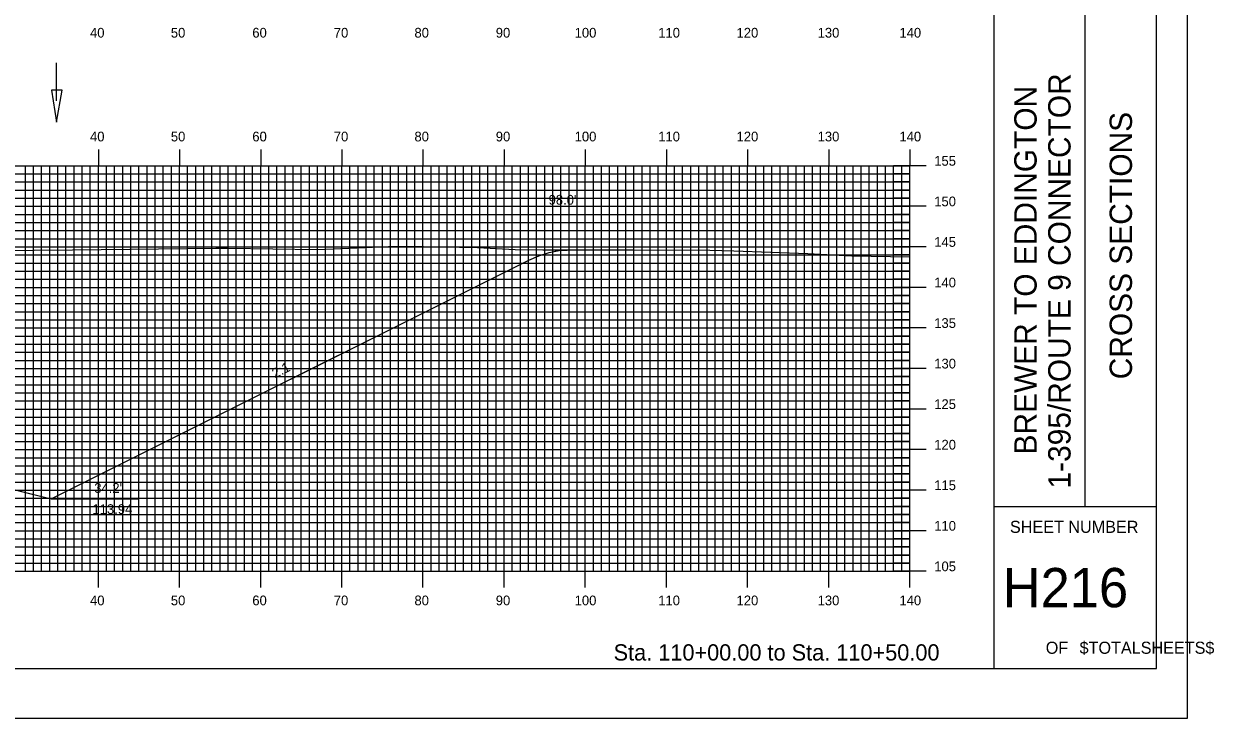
# Model space of a CAD drawing. Extents: x 1769268 to 1769611, y 442591 to 442811.
# Drawn here: x 1769464.3 to 1769611, y 442590.5 to 442676.2 of the extents above; entities that cross this region are included whole.
import ezdxf

# ---------------------------------------------------------------- set-up
doc = ezdxf.new("R2010")
doc.units = 0
for name, color, linetype in [('ANNOTATION', 7, 'Continuous'), ('BORDER', 7, 'Continuous'), ('D_Drainage_Ditch_Line', 7, 'Continuous'), ('D_Roadway_Centerline', 7, 'Continuous'), ('D_Roadway_SlopeLines', 7, 'Continuous'), ('D_Text_Standard', 7, 'Continuous'), ('H_V ANNOTATION', 7, 'Continuous'), ('MAJOR', 7, 'Continuous'), ('MINOR', 7, 'Continuous'), ('PDRAIN', 7, 'Continuous'), ('PLOT BOUNDARY', 7, 'Continuous'), ('S_Roadway_Centerline', 7, 'Continuous')]:
    doc.layers.add(name, color=color, linetype=linetype)

msp = doc.modelspace()

# ---------------------------------------------------------------- linework, layer by layer
at = {"layer": 'BORDER'}
for p, q in [((1769583.9, 442596.67), (1769583.9, 442806.67)), ((1769595.08, 442616.67), (1769595.08, 442686.67)), ((1769583.9, 442616.67), (1769603.9, 442616.67))]:
    msp.add_line(p, q, dxfattribs=at)
msp.add_lwpolyline([(1769283.9, 442596.67), (1769603.9, 442596.67), (1769603.9, 442806.67), (1769283.9, 442806.67)], close=True, dxfattribs=at)
at = {"layer": 'D_Drainage_Ditch_Line'}
msp.add_line((1769468.36, 442666.66), (1769468.36, 442671.36), dxfattribs=at)
msp.add_lwpolyline([(1769469.02, 442667.97), (1769467.71, 442667.97), (1769468.36, 442664.03)], close=True, dxfattribs=at)
at = {"layer": 'D_Roadway_Centerline'}
msp.add_lwpolyline([(1769463.68, 442618.6), (1769467.68, 442617.6), (1769467.68, 442617.6), (1769479.85, 442623.69), (1769526.54, 442647.04), (1769527.79, 442647.58), (1769529.04, 442647.97), (1769529.8, 442648.12), (1769530.29, 442648.21), (1769531.27, 442648.27), (1769531.54, 442648.29)], dxfattribs=at)
at = {"layer": 'D_Roadway_SlopeLines'}
for points in [[(1769467.68, 442617.6), (1769526.54, 442647.04), (1769527.79, 442647.58), (1769529.04, 442647.97), (1769530.29, 442648.21), (1769531.54, 442648.29)], [(1769453.5, 442621.15), (1769467.68, 442617.6)]]:
    msp.add_lwpolyline(points, dxfattribs=at)
at = {"layer": 'MAJOR'}
for p, q in [((1769473.5, 442660.67), (1769473.5, 442658.67)), ((1769483.5, 442660.67), (1769483.5, 442658.67)), ((1769493.5, 442660.67), (1769493.5, 442658.67)), ((1769503.5, 442660.67), (1769503.5, 442658.67)), ((1769513.5, 442660.67), (1769513.5, 442658.67)), ((1769523.5, 442660.67), (1769523.5, 442658.67)), ((1769533.5, 442660.67), (1769533.5, 442658.67)), ((1769543.5, 442660.67), (1769543.5, 442658.67)), ((1769553.5, 442660.67), (1769553.5, 442658.67)), ((1769563.5, 442660.67), (1769563.5, 442658.67)), ((1769573.5, 442660.67), (1769573.5, 442658.67)), ((1769293.5, 442658.67), (1769573.5, 442658.67)), ((1769293.5, 442658.67), (1769573.5, 442658.67)), ((1769473.5, 442608.67), (1769473.5, 442658.67)), ((1769483.5, 442608.67), (1769483.5, 442658.67)), ((1769493.5, 442608.67), (1769493.5, 442658.67)), ((1769503.5, 442608.67), (1769503.5, 442658.67)), ((1769513.5, 442608.67), (1769513.5, 442658.67)), ((1769523.5, 442608.67), (1769523.5, 442658.67)), ((1769533.5, 442608.67), (1769533.5, 442658.67)), ((1769543.5, 442608.67), (1769543.5, 442658.67)), ((1769553.5, 442608.67), (1769553.5, 442658.67)), ((1769563.5, 442608.67), (1769563.5, 442658.67)), ((1769575.51, 442658.67), (1769571.5, 442658.67)), ((1769573.5, 442608.67), (1769573.5, 442658.67)), ((1769573.5, 442608.67), (1769573.5, 442658.67)), ((1769293.5, 442653.67), (1769573.5, 442653.67)), ((1769575.51, 442653.67), (1769571.5, 442653.67)), ((1769293.5, 442648.67), (1769573.5, 442648.67)), ((1769575.51, 442648.67), (1769571.5, 442648.67)), ((1769293.5, 442643.67), (1769573.5, 442643.67)), ((1769575.51, 442643.67), (1769571.5, 442643.67)), ((1769293.5, 442638.67), (1769573.5, 442638.67)), ((1769575.51, 442638.67), (1769571.5, 442638.67)), ((1769293.5, 442633.67), (1769573.5, 442633.67)), ((1769575.51, 442633.67), (1769571.5, 442633.67)), ((1769293.5, 442628.67), (1769573.5, 442628.67)), ((1769575.51, 442628.67), (1769571.5, 442628.67)), ((1769293.5, 442623.67), (1769573.5, 442623.67)), ((1769575.51, 442623.67), (1769571.5, 442623.67)), ((1769293.5, 442618.67), (1769573.5, 442618.67)), ((1769575.51, 442618.67), (1769571.5, 442618.67)), ((1769293.5, 442613.67), (1769573.5, 442613.67)), ((1769575.51, 442613.67), (1769571.5, 442613.67)), ((1769293.5, 442608.67), (1769573.5, 442608.67)), ((1769293.5, 442608.67), (1769573.5, 442608.67)), ((1769473.5, 442606.66), (1769473.5, 442608.67)), ((1769483.5, 442606.66), (1769483.5, 442608.67)), ((1769493.5, 442606.66), (1769493.5, 442608.67)), ((1769503.5, 442606.66), (1769503.5, 442608.67)), ((1769513.5, 442606.66), (1769513.5, 442608.67)), ((1769523.5, 442606.66), (1769523.5, 442608.67)), ((1769533.5, 442606.66), (1769533.5, 442608.67)), ((1769543.5, 442606.66), (1769543.5, 442608.67)), ((1769553.5, 442606.66), (1769553.5, 442608.67)), ((1769563.5, 442606.66), (1769563.5, 442608.67)), ((1769575.51, 442608.67), (1769571.5, 442608.67)), ((1769573.5, 442606.66), (1769573.5, 442608.67))]:
    msp.add_line(p, q, dxfattribs=at)
at = {"layer": 'MINOR'}
for p, q in [((1769464.5, 442608.67), (1769464.5, 442658.67)), ((1769465.5, 442608.67), (1769465.5, 442658.67)), ((1769466.5, 442608.67), (1769466.5, 442658.67)), ((1769467.5, 442608.67), (1769467.5, 442658.67)), ((1769468.5, 442608.67), (1769468.5, 442658.67)), ((1769469.5, 442608.67), (1769469.5, 442658.67)), ((1769470.5, 442608.67), (1769470.5, 442658.67)), ((1769471.5, 442608.67), (1769471.5, 442658.67)), ((1769472.5, 442608.67), (1769472.5, 442658.67)), ((1769474.5, 442608.67), (1769474.5, 442658.67)), ((1769475.5, 442608.67), (1769475.5, 442658.67)), ((1769476.5, 442608.67), (1769476.5, 442658.67)), ((1769477.5, 442608.67), (1769477.5, 442658.67)), ((1769478.5, 442608.67), (1769478.5, 442658.67)), ((1769479.5, 442608.67), (1769479.5, 442658.67)), ((1769480.5, 442608.67), (1769480.5, 442658.67)), ((1769481.5, 442608.67), (1769481.5, 442658.67)), ((1769482.5, 442608.67), (1769482.5, 442658.67)), ((1769484.5, 442608.67), (1769484.5, 442658.67)), ((1769485.5, 442608.67), (1769485.5, 442658.67)), ((1769486.5, 442608.67), (1769486.5, 442658.67)), ((1769487.5, 442608.67), (1769487.5, 442658.67)), ((1769488.5, 442608.67), (1769488.5, 442658.67)), ((1769489.5, 442608.67), (1769489.5, 442658.67)), ((1769490.5, 442608.67), (1769490.5, 442658.67)), ((1769491.5, 442608.67), (1769491.5, 442658.67)), ((1769492.5, 442608.67), (1769492.5, 442658.67)), ((1769494.5, 442608.67), (1769494.5, 442658.67)), ((1769495.5, 442608.67), (1769495.5, 442658.67)), ((1769496.5, 442608.67), (1769496.5, 442658.67)), ((1769497.5, 442608.67), (1769497.5, 442658.67)), ((1769498.5, 442608.67), (1769498.5, 442658.67)), ((1769499.5, 442608.67), (1769499.5, 442658.67)), ((1769500.5, 442608.67), (1769500.5, 442658.67)), ((1769501.5, 442608.67), (1769501.5, 442658.67)), ((1769502.5, 442608.67), (1769502.5, 442658.67)), ((1769504.5, 442608.67), (1769504.5, 442658.67)), ((1769505.5, 442608.67), (1769505.5, 442658.67)), ((1769506.5, 442608.67), (1769506.5, 442658.67)), ((1769507.5, 442608.67), (1769507.5, 442658.67)), ((1769508.5, 442608.67), (1769508.5, 442658.67)), ((1769509.5, 442608.67), (1769509.5, 442658.67)), ((1769510.5, 442608.67), (1769510.5, 442658.67)), ((1769511.5, 442608.67), (1769511.5, 442658.67)), ((1769512.5, 442608.67), (1769512.5, 442658.67)), ((1769514.5, 442608.67), (1769514.5, 442658.67)), ((1769515.5, 442608.67), (1769515.5, 442658.67)), ((1769516.5, 442608.67), (1769516.5, 442658.67)), ((1769517.5, 442608.67), (1769517.5, 442658.67)), ((1769518.5, 442608.67), (1769518.5, 442658.67)), ((1769519.5, 442608.67), (1769519.5, 442658.67)), ((1769520.5, 442608.67), (1769520.5, 442658.67)), ((1769521.5, 442608.67), (1769521.5, 442658.67)), ((1769522.5, 442608.67), (1769522.5, 442658.67)), ((1769524.5, 442608.67), (1769524.5, 442658.67)), ((1769525.5, 442608.67), (1769525.5, 442658.67)), ((1769526.5, 442608.67), (1769526.5, 442658.67)), ((1769527.5, 442608.67), (1769527.5, 442658.67)), ((1769528.5, 442608.67), (1769528.5, 442658.67)), ((1769529.5, 442608.67), (1769529.5, 442658.67)), ((1769530.5, 442608.67), (1769530.5, 442658.67)), ((1769531.5, 442608.67), (1769531.5, 442658.67)), ((1769532.5, 442608.67), (1769532.5, 442658.67)), ((1769534.5, 442608.67), (1769534.5, 442658.67)), ((1769535.5, 442608.67), (1769535.5, 442658.67)), ((1769536.5, 442608.67), (1769536.5, 442658.67)), ((1769537.5, 442608.67), (1769537.5, 442658.67)), ((1769538.5, 442608.67), (1769538.5, 442658.67)), ((1769539.5, 442608.67), (1769539.5, 442658.67)), ((1769540.5, 442608.67), (1769540.5, 442658.67)), ((1769541.5, 442608.67), (1769541.5, 442658.67)), ((1769542.5, 442608.67), (1769542.5, 442658.67)), ((1769544.5, 442608.67), (1769544.5, 442658.67)), ((1769545.5, 442608.67), (1769545.5, 442658.67)), ((1769546.5, 442608.67), (1769546.5, 442658.67)), ((1769547.5, 442608.67), (1769547.5, 442658.67)), ((1769548.5, 442608.67), (1769548.5, 442658.67)), ((1769549.5, 442608.67), (1769549.5, 442658.67)), ((1769550.5, 442608.67), (1769550.5, 442658.67)), ((1769551.5, 442608.67), (1769551.5, 442658.67)), ((1769552.5, 442608.67), (1769552.5, 442658.67)), ((1769554.5, 442608.67), (1769554.5, 442658.67)), ((1769555.5, 442608.67), (1769555.5, 442658.67)), ((1769556.5, 442608.67), (1769556.5, 442658.67)), ((1769557.5, 442608.67), (1769557.5, 442658.67)), ((1769558.5, 442608.67), (1769558.5, 442658.67)), ((1769559.5, 442608.67), (1769559.5, 442658.67)), ((1769560.5, 442608.67), (1769560.5, 442658.67)), ((1769561.5, 442608.67), (1769561.5, 442658.67)), ((1769562.5, 442608.67), (1769562.5, 442658.67)), ((1769564.5, 442608.67), (1769564.5, 442658.67)), ((1769565.5, 442608.67), (1769565.5, 442658.67)), ((1769566.5, 442608.67), (1769566.5, 442658.67)), ((1769567.5, 442608.67), (1769567.5, 442658.67)), ((1769568.5, 442608.67), (1769568.5, 442658.67)), ((1769569.5, 442608.67), (1769569.5, 442658.67)), ((1769570.5, 442608.67), (1769570.5, 442658.67)), ((1769571.5, 442608.67), (1769571.5, 442658.67)), ((1769572.5, 442608.67), (1769572.5, 442658.67)), ((1769293.5, 442657.67), (1769573.5, 442657.67)), ((1769573.5, 442657.67), (1769571.5, 442657.67)), ((1769293.5, 442656.67), (1769573.5, 442656.67)), ((1769293.5, 442655.67), (1769573.5, 442655.67)), ((1769573.5, 442656.67), (1769571.5, 442656.67)), ((1769573.5, 442655.67), (1769571.5, 442655.67)), ((1769293.5, 442654.67), (1769573.5, 442654.67)), ((1769573.5, 442654.67), (1769571.5, 442654.67)), ((1769293.5, 442652.67), (1769573.5, 442652.67)), ((1769573.5, 442652.67), (1769571.5, 442652.67)), ((1769293.5, 442651.67), (1769573.5, 442651.67)), ((1769573.5, 442651.67), (1769571.5, 442651.67)), ((1769293.5, 442650.67), (1769573.5, 442650.67)), ((1769293.5, 442649.67), (1769573.5, 442649.67)), ((1769573.5, 442650.67), (1769571.5, 442650.67)), ((1769573.5, 442649.67), (1769571.5, 442649.67)), ((1769293.5, 442647.67), (1769573.5, 442647.67)), ((1769293.5, 442646.67), (1769573.5, 442646.67)), ((1769573.5, 442647.67), (1769571.5, 442647.67)), ((1769573.5, 442646.67), (1769571.5, 442646.67)), ((1769293.5, 442645.67), (1769573.5, 442645.67)), ((1769573.5, 442645.67), (1769571.5, 442645.67)), ((1769293.5, 442644.67), (1769573.5, 442644.67)), ((1769573.5, 442644.67), (1769571.5, 442644.67)), ((1769293.5, 442642.67), (1769573.5, 442642.67)), ((1769573.5, 442642.67), (1769571.5, 442642.67)), ((1769293.5, 442641.67), (1769573.5, 442641.67)), ((1769293.5, 442640.67), (1769573.5, 442640.67)), ((1769573.5, 442641.67), (1769571.5, 442641.67)), ((1769573.5, 442640.67), (1769571.5, 442640.67)), ((1769293.5, 442639.67), (1769573.5, 442639.67)), ((1769573.5, 442639.67), (1769571.5, 442639.67)), ((1769293.5, 442637.67), (1769573.5, 442637.67)), ((1769573.5, 442637.67), (1769571.5, 442637.67)), ((1769293.5, 442636.67), (1769573.5, 442636.67)), ((1769573.5, 442636.67), (1769571.5, 442636.67)), ((1769293.5, 442635.67), (1769573.5, 442635.67)), ((1769573.5, 442635.67), (1769571.5, 442635.67)), ((1769293.5, 442634.67), (1769573.5, 442634.67)), ((1769573.5, 442634.67), (1769571.5, 442634.67)), ((1769293.5, 442632.67), (1769573.5, 442632.67)), ((1769573.5, 442632.67), (1769571.5, 442632.67)), ((1769293.5, 442631.67), (1769573.5, 442631.67)), ((1769293.5, 442630.67), (1769573.5, 442630.67)), ((1769573.5, 442631.67), (1769571.5, 442631.67)), ((1769573.5, 442630.67), (1769571.5, 442630.67)), ((1769293.5, 442629.67), (1769573.5, 442629.67)), ((1769573.5, 442629.67), (1769571.5, 442629.67)), ((1769293.5, 442627.67), (1769573.5, 442627.67)), ((1769573.5, 442627.67), (1769571.5, 442627.67)), ((1769293.5, 442626.67), (1769573.5, 442626.67)), ((1769573.5, 442626.67), (1769571.5, 442626.67)), ((1769293.5, 442625.67), (1769573.5, 442625.67)), ((1769293.5, 442624.67), (1769573.5, 442624.67)), ((1769573.5, 442625.67), (1769571.5, 442625.67)), ((1769573.5, 442624.67), (1769571.5, 442624.67)), ((1769293.5, 442622.67), (1769573.5, 442622.67)), ((1769293.5, 442621.67), (1769573.5, 442621.67)), ((1769573.5, 442622.67), (1769571.5, 442622.67)), ((1769573.5, 442621.67), (1769571.5, 442621.67)), ((1769293.5, 442620.67), (1769573.5, 442620.67)), ((1769573.5, 442620.67), (1769571.5, 442620.67)), ((1769293.5, 442619.67), (1769573.5, 442619.67)), ((1769573.5, 442619.67), (1769571.5, 442619.67)), ((1769293.5, 442617.67), (1769573.5, 442617.67)), ((1769573.5, 442617.67), (1769571.5, 442617.67)), ((1769293.5, 442616.67), (1769573.5, 442616.67)), ((1769293.5, 442615.67), (1769573.5, 442615.67)), ((1769573.5, 442616.67), (1769571.5, 442616.67)), ((1769573.5, 442615.67), (1769571.5, 442615.67)), ((1769293.5, 442614.67), (1769573.5, 442614.67)), ((1769573.5, 442614.67), (1769571.5, 442614.67)), ((1769293.5, 442612.67), (1769573.5, 442612.67)), ((1769293.5, 442611.67), (1769573.5, 442611.67)), ((1769573.5, 442612.67), (1769571.5, 442612.67)), ((1769573.5, 442611.67), (1769571.5, 442611.67)), ((1769293.5, 442610.67), (1769573.5, 442610.67)), ((1769573.5, 442610.67), (1769571.5, 442610.67)), ((1769293.5, 442609.67), (1769573.5, 442609.67)), ((1769573.5, 442609.67), (1769571.5, 442609.67))]:
    msp.add_line(p, q, dxfattribs=at)
at = {"layer": 'PDRAIN'}
msp.add_line((1769467.68, 442617.6), (1769478.45, 442617.6), dxfattribs=at)
at = {"layer": 'PLOT BOUNDARY'}
msp.add_lwpolyline([(1769267.72, 442590.55), (1769607.72, 442590.55), (1769607.72, 442810.55), (1769267.72, 442810.55)], close=True, dxfattribs=at)
at = {"layer": 'S_Roadway_Centerline'}
msp.add_lwpolyline([(1769456.07, 442648.17), (1769470.31, 442648.28), (1769487.99, 442648.52), (1769489.53, 442648.51), (1769500.48, 442648.33), (1769509.26, 442648.72), (1769513.56, 442648.72), (1769520.23, 442648.58), (1769524.87, 442648.36), (1769528.27, 442648.29), (1769539.51, 442648.29), (1769548.86, 442648.24), (1769551.8, 442648.17), (1769560.91, 442647.84), (1769566.35, 442647.55), (1769573.5, 442647.44)], dxfattribs=at)

# ---------------------------------------------------------------- texts
at = {"layer": 'ANNOTATION'}
msp.add_text('2:1', height=1.2, rotation=26.5652, dxfattribs=at).set_placement((1769495.26, 442632.43))
for s, p in [("34.2'", (1769472.99, 442618.33)), ('113.94', (1769472.77, 442615.73))]:
    msp.add_text(s, height=1.2, dxfattribs=at).set_placement(p)
at = {"layer": 'BORDER'}
for s, p in [('1-395/ROUTE 9 CONNECTOR', (1769593.3, 442618.87)), ('BREWER TO EDDINGTON', (1769589.12, 442623.07)), ('CROSS SECTIONS', (1769600.87, 442632.34))]:
    msp.add_text(s, height=2.7557, rotation=90, dxfattribs=at).set_placement(p)
for s, height, p in [('SHEET NUMBER', 1.4905, (1769585.83, 442613.4)), ('H216', 4.839, (1769584.93, 442604.23)), ('OF', 1.491, (1769590.24, 442598.49)), ('$TOTALSHEETS$', 1.4905, (1769594.41, 442598.49))]:
    msp.add_text(s, height=height, dxfattribs=at).set_placement(p)
at = {"layer": 'D_Text_Standard'}
msp.add_text("98.0'", height=1.2, dxfattribs=at).set_placement((1769528.98, 442653.87))
at = {"layer": 'H_V ANNOTATION'}
for s, height, p in [('40', 1.2, (1769472.47, 442674.47)), ('50', 1.2, (1769482.43, 442674.47)), ('60', 1.2, (1769492.47, 442674.47)), ('70', 1.2, (1769502.51, 442674.47)), ('80', 1.2, (1769512.45, 442674.47)), ('90', 1.2, (1769522.47, 442674.47)), ('100', 1.2, (1769532.19, 442674.47)), ('110', 1.2, (1769542.49, 442674.47)), ('120', 1.2, (1769552.14, 442674.47)), ('130', 1.2, (1769562.13, 442674.47)), ('140', 1.2, (1769572.21, 442674.47)), ('40', 1.2, (1769472.47, 442661.67)), ('50', 1.2, (1769482.43, 442661.67)), ('60', 1.2, (1769492.47, 442661.67)), ('70', 1.2, (1769502.51, 442661.67)), ('80', 1.2, (1769512.45, 442661.67)), ('90', 1.2, (1769522.47, 442661.67)), ('100', 1.2, (1769532.19, 442661.67)), ('110', 1.2, (1769542.49, 442661.67)), ('120', 1.2, (1769552.14, 442661.67)), ('130', 1.2, (1769562.13, 442661.67)), ('140', 1.2, (1769572.21, 442661.67)), ('155', 1.2, (1769576.5, 442658.67)), ('150', 1.2, (1769576.5, 442653.67)), ('145', 1.2, (1769576.5, 442648.67)), ('140', 1.2, (1769576.5, 442643.67)), ('135', 1.2, (1769576.5, 442638.67)), ('130', 1.2, (1769576.5, 442633.67)), ('125', 1.2, (1769576.5, 442628.67)), ('120', 1.2, (1769576.5, 442623.67)), ('115', 1.2, (1769576.5, 442618.67)), ('110', 1.2, (1769576.5, 442613.67)), ('105', 1.2, (1769576.5, 442608.67)), ('40', 1.2, (1769472.47, 442604.47)), ('50', 1.2, (1769482.43, 442604.47)), ('60', 1.2, (1769492.47, 442604.47)), ('70', 1.2, (1769502.51, 442604.47)), ('80', 1.2, (1769512.45, 442604.47)), ('90', 1.2, (1769522.47, 442604.47)), ('100', 1.2, (1769532.19, 442604.47)), ('110', 1.2, (1769542.49, 442604.47)), ('120', 1.2, (1769552.14, 442604.47)), ('130', 1.2, (1769562.13, 442604.47)), ('140', 1.2, (1769572.21, 442604.47)), ('Sta. 110+00.00 to Sta. 110+50.00', 2.0004, (1769536.99, 442597.66))]:
    msp.add_text(s, height=height, dxfattribs=at).set_placement(p)

doc.saveas('drawing.dxf')
